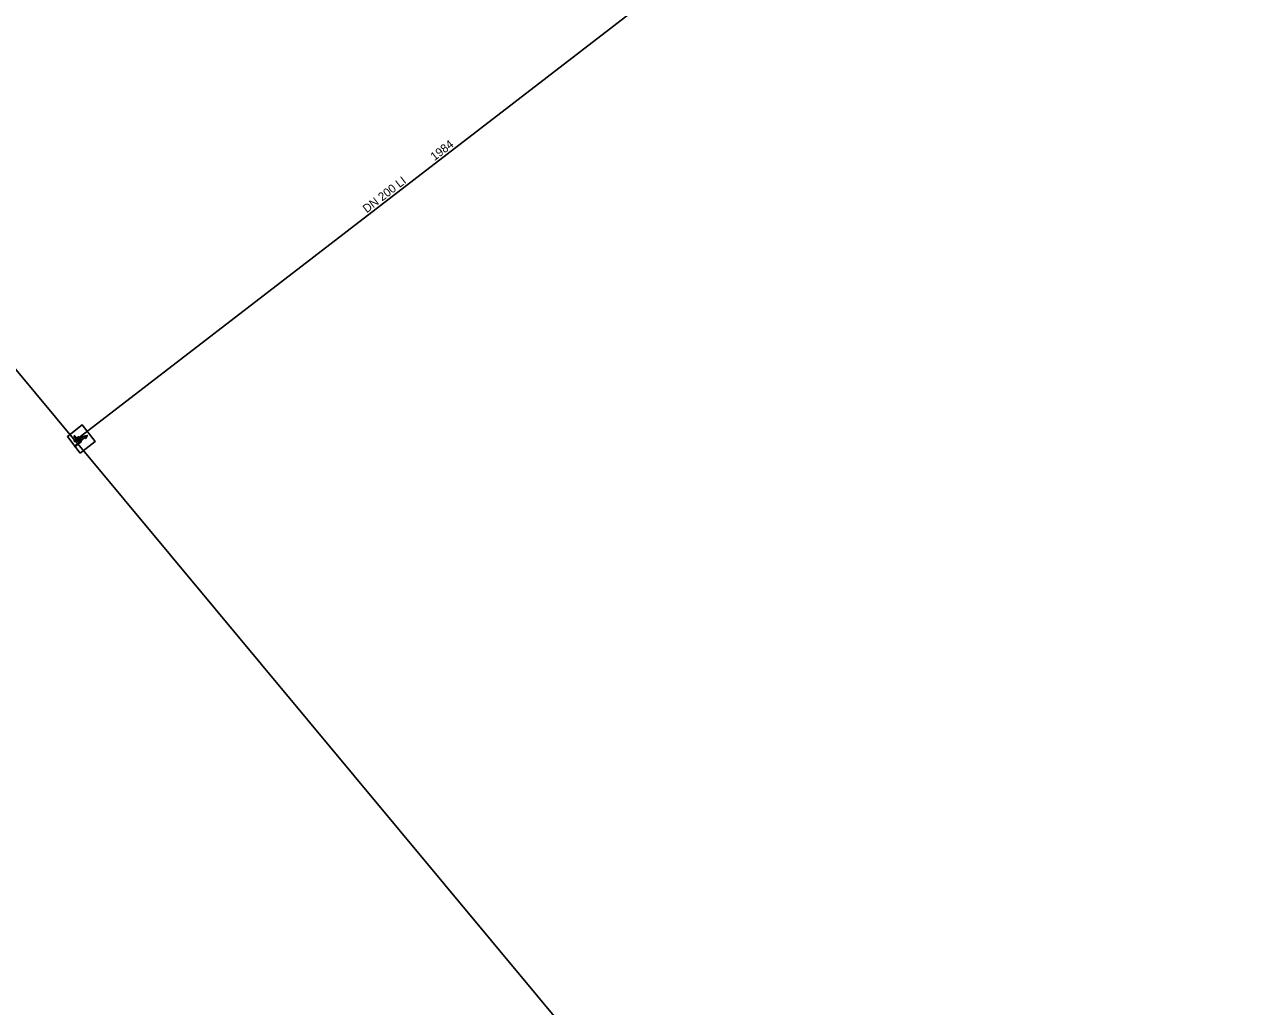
# Model space of a CAD drawing. Extents: x -595129 to -593591, y -1168385 to -1166898.
# Drawn here: x -594687.5 to -594399.5, y -1168151.9 to -1167918.9 of the extents above; entities that cross this region are included whole.
import ezdxf

# ---------------------------------------------------------------- set-up
doc = ezdxf.new("R2010")
doc.units = 0
for name, color, linetype in [('DA V Řad popis', 7, 'Continuous'), ('DA V Řad přejímka', 7, 'Continuous'), ('Default', 7, 'Continuous'), ('V Uzávěr', 7, 'Continuous'), ('V Řad', 7, 'Continuous'), ('VP Podzemní obvod objektu', 7, 'Continuous')]:
    doc.layers.add(name, color=color, linetype=linetype)

msp = doc.modelspace()

# ---------------------------------------------------------------- linework, layer by layer
at = {"layer": 'Default'}
for points in [[(-594675.4, -1168017.39), (-594675.34, -1168017.39), (-594675.28, -1168017.42), (-594675.22, -1168017.45), (-594675.19, -1168017.51), (-594675.15, -1168017.57), (-594675.15, -1168017.64), (-594675.15, -1168017.7), (-594675.19, -1168017.76), (-594675.22, -1168017.82), (-594675.28, -1168017.85), (-594675.34, -1168017.89), (-594675.4, -1168017.89), (-594675.47, -1168017.89), (-594675.53, -1168017.85), (-594675.59, -1168017.82), (-594675.62, -1168017.76), (-594675.65, -1168017.7), (-594675.65, -1168017.64), (-594675.65, -1168017.57), (-594675.62, -1168017.51), (-594675.59, -1168017.45), (-594675.53, -1168017.42), (-594675.47, -1168017.39), (-594675.4, -1168017.39)], [(-594675.4, -1168017.42), (-594675.46, -1168017.42), (-594675.51, -1168017.45), (-594675.56, -1168017.47), (-594675.59, -1168017.53), (-594675.62, -1168017.58), (-594675.62, -1168017.64), (-594675.62, -1168017.69), (-594675.59, -1168017.75), (-594675.56, -1168017.8), (-594675.51, -1168017.83), (-594675.46, -1168017.85), (-594675.4, -1168017.85), (-594675.35, -1168017.85), (-594675.29, -1168017.83), (-594675.24, -1168017.8), (-594675.21, -1168017.75), (-594675.18, -1168017.69), (-594675.18, -1168017.64), (-594675.18, -1168017.58), (-594675.21, -1168017.53), (-594675.24, -1168017.47), (-594675.3, -1168017.45), (-594675.35, -1168017.42), (-594675.4, -1168017.42)], [(-594674.63, -1168016.74), (-594674.56, -1168016.74), (-594674.5, -1168016.77), (-594674.44, -1168016.8), (-594674.41, -1168016.86), (-594674.38, -1168016.92), (-594674.38, -1168016.99), (-594674.38, -1168017.05), (-594674.41, -1168017.11), (-594674.44, -1168017.17), (-594674.5, -1168017.21), (-594674.56, -1168017.24), (-594674.63, -1168017.24), (-594674.69, -1168017.24), (-594674.75, -1168017.21), (-594674.81, -1168017.17), (-594674.84, -1168017.11), (-594674.88, -1168017.05), (-594674.88, -1168016.99), (-594674.88, -1168016.92), (-594674.84, -1168016.86), (-594674.81, -1168016.8), (-594674.75, -1168016.77), (-594674.69, -1168016.74), (-594674.63, -1168016.74)], [(-594674.63, -1168016.77), (-594674.68, -1168016.77), (-594674.73, -1168016.8), (-594674.79, -1168016.83), (-594674.82, -1168016.88), (-594674.84, -1168016.93), (-594674.84, -1168016.99), (-594674.84, -1168017.05), (-594674.82, -1168017.1), (-594674.79, -1168017.15), (-594674.74, -1168017.18), (-594674.68, -1168017.21), (-594674.63, -1168017.21), (-594674.57, -1168017.21), (-594674.52, -1168017.18), (-594674.46, -1168017.15), (-594674.44, -1168017.1), (-594674.41, -1168017.05), (-594674.41, -1168016.99), (-594674.41, -1168016.93), (-594674.44, -1168016.88), (-594674.47, -1168016.83), (-594674.52, -1168016.8), (-594674.57, -1168016.77), (-594674.63, -1168016.77)]]:
    msp.add_open_spline(points, degree=3, dxfattribs=at)
at = {"layer": 'V Uzávěr'}
for points in [[(-594675.71, -1168016.59), (-594675.57, -1168016.47), (-594674.29, -1168018.01), (-594674.43, -1168018.13), (-594675.71, -1168016.59)], [(-594674.06, -1168017.69), (-594673.94, -1168017.83), (-594675.47, -1168019.11), (-594675.59, -1168018.97), (-594674.06, -1168017.69)], [(-594673.7, -1168016.54), (-594673.58, -1168016.68), (-594675.12, -1168017.96), (-594675.24, -1168017.82), (-594673.7, -1168016.54)], [(-594674.06, -1168017.53), (-594673.2, -1168016.81), (-594673.39, -1168016.57), (-594672.57, -1168016.38), (-594672.91, -1168017.15), (-594673.12, -1168016.9), (-594674.08, -1168017.7), (-594674.43, -1168017.27), (-594674.34, -1168017.19), (-594674.06, -1168017.53)], [(-594673.05, -1168016.61), (-594673.17, -1168016.64), (-594672.94, -1168016.92), (-594672.89, -1168016.81), (-594673.05, -1168016.61)], [(-594672.83, -1168016.68), (-594672.78, -1168016.55), (-594672.92, -1168016.58), (-594672.83, -1168016.68)]]:
    msp.add_lwpolyline(points, dxfattribs=at)
at = {"layer": 'V Řad'}
msp.add_line((-594674.63, -1168016.99), (-594674.41, -1168017.25), dxfattribs=at)
for points in [[(-594675, -1168017.3), (-594674.63, -1168016.99), (-594674.19, -1168016.62), (-594500.19, -1167882.67), (-594499.19, -1167881.9), (-594497.3, -1167880.45), (-594496.9, -1167880.14)], [(-594754.37, -1167922.75), (-594675.4, -1168017.64)], [(-594675.4, -1168017.64), (-594675, -1168017.3)], [(-594675.4, -1168017.64), (-594674.77, -1168018.4)], [(-594674.77, -1168018.4), (-594369.49, -1168385.25)]]:
    msp.add_lwpolyline(points, dxfattribs=at)
at = {"layer": 'VP Podzemní obvod objektu'}
msp.add_lwpolyline([(-594674.2, -1168020.57), (-594670.67, -1168017.8), (-594673.74, -1168013.89), (-594677.27, -1168016.67)], close=True, dxfattribs=at)

# ---------------------------------------------------------------- texts
at = {"layer": 'DA V Řad popis'}
msp.add_text('DN 200 LI', height=2, rotation=37.586, dxfattribs=at).set_placement((-594606.26, -1167963.72))
at = {"layer": 'DA V Řad přejímka'}
msp.add_text('1984', height=2, rotation=37.586, dxfattribs=at).set_placement((-594590.19, -1167951.35))

doc.saveas('drawing.dxf')
